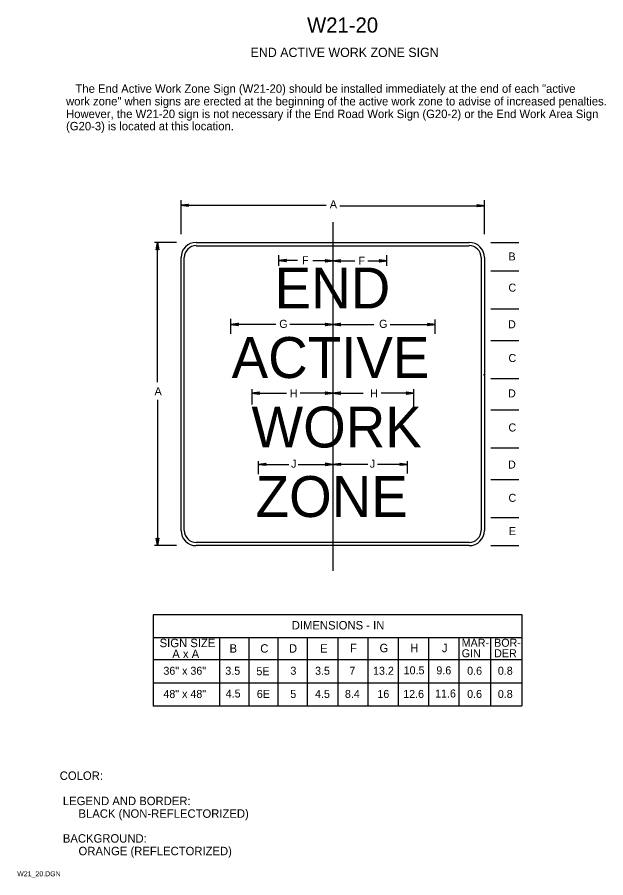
# Model space of a CAD drawing. Extents: x 0.013 to 0.187, y 0.004 to 0.259.
import ezdxf

# ---------------------------------------------------------------- set-up
doc = ezdxf.new("R2010")
doc.units = 0
for name, color, linetype in [('1', 7, 'Continuous'), ('2', 7, 'Continuous'), ('3', 7, 'Continuous')]:
    doc.layers.add(name, color=color, linetype=linetype)

# ---------------------------------------------------------------- blocks, each defined once
blk = doc.blocks.new('RARROW')
at = {"layer": '3'}
for p, q in [((-2.156, 0.285), (-2.2665, 0.384625)), ((-2.2665, 0.384625), (0, 0)), ((0, 0), (-2.2665, -0.379125)), ((-2.156, 0.285), (-2.075625, 0.12075)), ((0, 0), (-2.156, 0.285)), ((-2.14975, -0.2705), (0, 0)), ((-2.075625, 0.12075), (0, 0)), ((0, 0), (-2.074, -0.108)), ((-2.2665, -0.379125), (-2.14975, -0.2705)), ((-2.074, -0.108), (-2.14975, -0.2705))]:
    blk.add_line(p, q, dxfattribs=at)

msp = doc.modelspace()

# ---------------------------------------------------------------- linework, layer by layer
at = {"layer": '1'}
for p, q in [((0.10624, 0.19847), (0.10624, 0.09507)), ((0.0902, 0.18874), (0.0902, 0.18554)), ((0.12221, 0.18874), (0.12221, 0.18554)), ((0.07594, 0.16978), (0.07594, 0.16535)), ((0.13657, 0.1696), (0.13657, 0.16535)), ((0.15093, 0.15312), (0.15124, 0.15344)), ((0.08221, 0.14892), (0.08221, 0.14442)), ((0.13024, 0.14892), (0.13024, 0.1433)), ((0.08411, 0.12758), (0.08411, 0.12376)), ((0.12836, 0.12758), (0.12836, 0.12387)), ((0.16239, 0.08205), (0.16239, 0.05492)), ((0.14364, 0.07517), (0.14364, 0.05492)), ((0.15301, 0.07517), (0.15301, 0.05492))]:
    msp.add_line(p, q, dxfattribs=at)
at = {"layer": '2'}
for p, q in [((0.06574, 0.1925), (0.14674, 0.1925)), ((0.06124, 0.107), (0.06124, 0.188)), ((0.15124, 0.188), (0.15124, 0.107)), ((0.14674, 0.1025), (0.06574, 0.1025)), ((0.05293, 0.08205), (0.16239, 0.08205)), ((0.053, 0.082), (0.053, 0.05488)), ((0.16239, 0.07517), (0.05293, 0.07517)), ((0.07264, 0.07517), (0.07264, 0.05492)), ((0.08138, 0.07513), (0.08138, 0.05488)), ((0.09, 0.07513), (0.09, 0.05488)), ((0.09863, 0.07513), (0.09863, 0.05488)), ((0.10775, 0.07513), (0.10775, 0.05488)), ((0.11663, 0.07513), (0.11663, 0.05488)), ((0.12563, 0.07513), (0.12563, 0.05488)), ((0.13463, 0.07513), (0.13463, 0.05488)), ((0.05293, 0.06867), (0.16239, 0.06867)), ((0.05293, 0.0618), (0.16239, 0.0618)), ((0.05293, 0.05492), (0.16239, 0.05492))]:
    msp.add_line(p, q, dxfattribs=at)
for centre, start, end in [((0.06574, 0.188), 90, 180), ((0.14674, 0.188), 0, 90), ((0.06574, 0.107), 180, 270), ((0.14674, 0.107), 270, 0)]:
    msp.add_arc(centre, 0.0045, start, end, dxfattribs=at)
at = {"layer": '3'}
for p, q in [((0.06124, 0.19498), (0.06124, 0.20503)), ((0.15124, 0.19498), (0.15124, 0.20503)), ((0.1043, 0.20348), (0.06124, 0.20348)), ((0.10832, 0.20339), (0.15124, 0.20339)), ((0.05993, 0.1925), (0.05336, 0.1925)), ((0.05421, 0.15101), (0.05421, 0.19251)), ((0.15311, 0.1925), (0.16146, 0.1925)), ((0.06574, 0.19152), (0.14674, 0.19152)), ((0.06221, 0.107), (0.06221, 0.188)), ((0.09578, 0.18712), (0.0902, 0.18712)), ((0.10624, 0.187), (0.10032, 0.187)), ((0.10624, 0.187), (0.11284, 0.187)), ((0.11666, 0.18698), (0.12221, 0.18698)), ((0.15026, 0.188), (0.15026, 0.107)), ((0.15311, 0.18402), (0.16146, 0.18402)), ((0.15311, 0.17277), (0.16146, 0.17277)), ((0.08938, 0.16813), (0.07594, 0.16813)), ((0.10624, 0.16813), (0.09355, 0.16813)), ((0.10624, 0.16813), (0.1184, 0.16813)), ((0.12327, 0.16813), (0.13654, 0.16813)), ((0.15311, 0.1634), (0.16146, 0.1634)), ((0.15311, 0.15215), (0.16146, 0.15215)), ((0.05421, 0.14579), (0.05421, 0.10251)), ((0.08224, 0.14774), (0.09249, 0.14774)), ((0.10624, 0.14775), (0.09659, 0.14775)), ((0.10624, 0.14775), (0.11527, 0.14775)), ((0.13024, 0.14775), (0.12066, 0.14775)), ((0.15311, 0.14277), (0.16146, 0.14277)), ((0.15311, 0.13152), (0.16146, 0.13152)), ((0.08411, 0.12662), (0.0932, 0.12662)), ((0.09602, 0.12662), (0.10624, 0.12662)), ((0.1167, 0.12662), (0.10624, 0.12662)), ((0.12836, 0.12662), (0.11951, 0.12662)), ((0.15311, 0.12215), (0.16146, 0.12215)), ((0.15311, 0.1109), (0.16146, 0.1109)), ((0.05993, 0.1025), (0.05336, 0.1025)), ((0.14674, 0.10347), (0.06574, 0.10347)), ((0.15311, 0.1025), (0.16146, 0.1025))]:
    msp.add_line(p, q, dxfattribs=at)
for centre, start, end in [((0.06574, 0.188), 90, 180), ((0.14674, 0.188), 0, 90), ((0.06574, 0.107), 180, 270), ((0.14674, 0.107), 270, 0)]:
    msp.add_arc(centre, 0.00353, start, end, dxfattribs=at)

# ---------------------------------------------------------------- block references
at = {"layer": '3', "xscale": 0.0009927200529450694, "yscale": 0.0009819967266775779}
for p, rotation in [((0.06125, 0.2035), 180), ((0.05425, 0.1925), 90), ((0.09025, 0.18713), 180), ((0.10625, 0.187), 180), ((0.076, 0.16813), 180), ((0.10625, 0.16813), 180), ((0.08225, 0.14775), 180), ((0.10625, 0.14775), 180), ((0.08425, 0.12663), 180), ((0.10638, 0.12663), 180), ((0.05425, 0.1025), -90)]:
    msp.add_blockref('RARROW', p, dxfattribs=dict(at, rotation=rotation))
at = {"layer": '3', "xscale": 0.0009927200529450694}
for p, yscale in [((0.15125, 0.20338), 0.0009819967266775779), ((0.10625, 0.187), 0.0009819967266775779), ((0.12225, 0.187), 0.0009819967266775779), ((0.10625, 0.16813), 0.0009819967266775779), ((0.13663, 0.16813), 0.0009819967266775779), ((0.10625, 0.14775), 0.0009819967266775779), ((0.13025, 0.14775), 0.0009819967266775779), ((0.10625, 0.12663), -0.0009819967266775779), ((0.12838, 0.12663), 0.0009819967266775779)]:
    msp.add_blockref('RARROW', p, dxfattribs=dict(at, yscale=yscale))

# ---------------------------------------------------------------- texts
at = {"layer": '1'}
for s, height, p in [('W21-20', 0.0045, (0.09863, 0.25475)), ('END ACTIVE WORK ZONE SIGN', 0.0027503, (0.08188, 0.2475)), ('END', 0.012149, (0.089, 0.17288)), ('ACTIVE', 0.012149, (0.07625, 0.15225)), ('WORK', 0.012149, (0.08213, 0.13163)), ('ZONE', 0.012149, (0.08338, 0.111)), ('MAR-', 0.002375, (0.1445, 0.0725)), ('BOR-', 0.002375, (0.15413, 0.0725)), ('GIN', 0.002375, (0.1445, 0.06938)), ('DER', 0.002375, (0.15413, 0.06938)), ('COLOR:', 0.0025, (0.02525, 0.033)), (' LEGEND AND BORDER:', 0.0024998, (0.02525, 0.0255)), ('      BLACK (NON-REFLECTORIZED)', 0.0024998, (0.02525, 0.02175)), (' BACKGROUND:', 0.0024998, (0.02525, 0.01438)), ('      ORANGE (REFLECTORIZED)', 0.0024998, (0.02525, 0.01063)), ('W21_20.DGN', 0.0015, (0.01263, 0.00438))]:
    msp.add_text(s, height=height, dxfattribs=at).set_placement(p)
at = {"layer": '2'}
for s, height, p in [('   The End Active Work Zone Sign (W21-20) should be installed immediately at the end of each "active', 0.0024998, (0.02713, 0.23688)), ('work zone" when signs are erected at the beginning of the active work zone to advise of increased penalties.', 0.00249975, (0.02713, 0.23313)), ('However, the W21-20 sign is not necessary if the End Road Work Sign (G20-2) or the End Work Area Sign', 0.00249975, (0.02713, 0.22938)), ('(G20-3) is located at this location.', 0.0024998, (0.02713, 0.22575)), ('DIMENSIONS - IN', 0.0024998, (0.09408, 0.07763)), ('SIGN SIZE', 0.0025, (0.05488, 0.07238)), ('A x A', 0.0025, (0.05863, 0.06913)), ('B', 0.0025, (0.07563, 0.07075)), ('C', 0.0025, (0.08475, 0.07075)), ('D', 0.0025, (0.09325, 0.07075)), ('E', 0.0025, (0.1025, 0.07075)), ('F', 0.0025, (0.11138, 0.07088)), ('G', 0.0025, (0.12013, 0.07088)), ('H', 0.0025, (0.12925, 0.07088)), ('J', 0.0025, (0.13863, 0.07088))]:
    msp.add_text(s, height=height, dxfattribs=at).set_placement(p)
at = {"layer": '3'}
for s, height, p in [('A', 0.00238, (0.10538, 0.20263)), ('B', 0.00238, (0.15838, 0.18713)), ('F', 0.00238, (0.09713, 0.186)), ('F', 0.00238, (0.11388, 0.18588)), ('C', 0.00238, (0.15838, 0.17788)), ('G', 0.00238, (0.09038, 0.16713)), ('G', 0.00238, (0.12, 0.16713)), ('D', 0.00238, (0.15825, 0.167)), ('C', 0.00238, (0.15838, 0.157)), ('A', 0.00238, (0.05338, 0.14713)), ('H', 0.00238, (0.0935, 0.1465)), ('H', 0.00238, (0.11738, 0.1465)), ('D', 0.00238, (0.15825, 0.1465)), ('C', 0.00238, (0.15838, 0.13638)), ('J', 0.00238, (0.09388, 0.12563)), ('J', 0.00238, (0.11725, 0.12563)), ('D', 0.00238, (0.15825, 0.12538)), ('C', 0.00238, (0.15838, 0.1155)), ('E', 0.00238, (0.1585, 0.10563)), ('36" x 36"', 0.002375, (0.056, 0.06419)), ('3.5', 0.002375, (0.07437, 0.06419)), ('5E', 0.002375, (0.0836, 0.06406)), ('3', 0.00238, (0.09368, 0.06419)), ('3.5', 0.002375, (0.101, 0.06419)), ('7', 0.00238, (0.11118, 0.06419)), ('13.2', 0.002375, (0.1182, 0.06419)), ('10.5', 0.002375, (0.12728, 0.06431)), ('9.6', 0.002375, (0.13699, 0.06431)), ('0.6', 0.002375, (0.14612, 0.06419)), ('0.8', 0.002375, (0.15523, 0.06419)), ('48" x 48"', 0.002375, (0.056, 0.05731)), ('4.5', 0.002375, (0.0745, 0.05744)), ('6E', 0.002375, (0.08372, 0.05731)), ('5', 0.00238, (0.09365, 0.05731)), ('4.5', 0.002375, (0.101, 0.05731)), ('8.4', 0.002375, (0.10986, 0.05731)), ('16', 0.002375, (0.11949, 0.05731)), ('12.6', 0.002375, (0.12715, 0.05731)), ('11.6', 0.002375, (0.13661, 0.05744)), ('0.6', 0.002375, (0.14612, 0.05731)), ('0.8', 0.002375, (0.15523, 0.05731))]:
    msp.add_text(s, height=height, dxfattribs=at).set_placement(p)

doc.saveas('drawing.dxf')
